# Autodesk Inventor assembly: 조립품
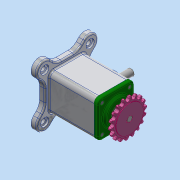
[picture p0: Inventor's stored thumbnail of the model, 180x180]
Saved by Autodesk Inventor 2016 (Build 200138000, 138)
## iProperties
Created: 2019-11
Part Number: 조립품
Material: 일반
Document SubType Name: Assembly
Designer: user
Author: user
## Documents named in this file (11)
- C:\Users\user\Desktop\491109V1011\조립품.iam
- C:\Users\user\Desktop\491109V1011\베어링 6203.ipt
- C:\Users\user\Desktop\491109V1011\본체.ipt
- C:\Users\user\Desktop\491109V1011\볼트 M4.ipt
- C:\Users\user\Desktop\491109V1011\부시.ipt
- C:\Users\user\Desktop\491109V1011\스프로킷.ipt
- C:\Users\user\Desktop\491109V1011\슬라이더.ipt
- C:\Users\user\Desktop\491109V1011\오일 실.ipt
- C:\Users\user\Desktop\491109V1011\커버.ipt
- C:\Users\user\Desktop\491109V1011\키 4 x 4 x 14.ipt
- C:\Users\user\Desktop\491109V1011\편심축.ipt
